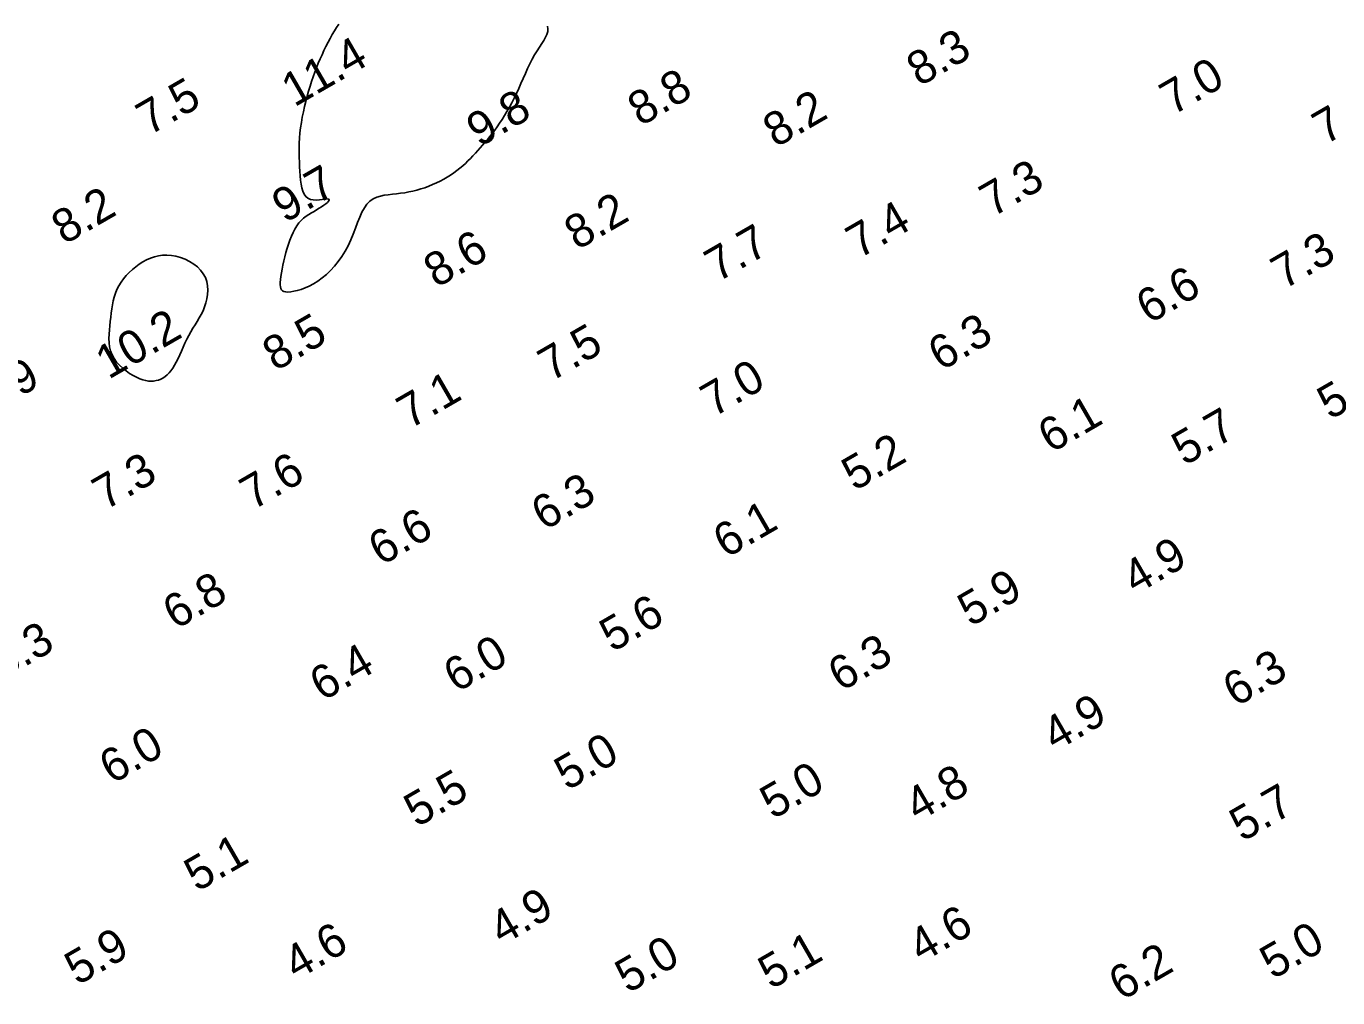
# Model space of a CAD drawing. Extents: x 3024098 to 3056816, y 418252 to 509144.
# Drawn here: x 3036706.3 to 3036901.9, y 419261.4 to 419406.4 of the extents above; entities that cross this region are included whole.
import ezdxf

# ---------------------------------------------------------------- set-up
doc = ezdxf.new("R2010")
doc.units = 0
doc.layers.add('V-CHAN-CONT-EL10', color=7, linetype='Continuous')
doc.layers.add('V-TOPO-SOUN-0911', color=7, linetype='Continuous')

msp = doc.modelspace()

# ---------------------------------------------------------------- linework, layer by layer
at = {"layer": 'V-CHAN-CONT-EL10'}
msp.add_lwpolyline([(3036784.03, 419406.41), (3036784.1, 419406.01), (3036784.07, 419405.6), (3036783.94, 419405.18), (3036783.74, 419404.74), (3036783.48, 419404.28), (3036783.17, 419403.79), (3036782.83, 419403.27), (3036782.47, 419402.71), (3036782.11, 419402.11), (3036781.75, 419401.47), (3036781.41, 419400.78), (3036781.07, 419400.06), (3036780.74, 419399.32), (3036780.41, 419398.57), (3036780.07, 419397.82), (3036779.74, 419397.08), (3036779.4, 419396.35), (3036779.05, 419395.64), (3036778.7, 419394.95), (3036778.34, 419394.29), (3036777.98, 419393.66), (3036777.62, 419393.05), (3036777.25, 419392.47), (3036776.88, 419391.92), (3036776.52, 419391.38), (3036776.15, 419390.88), (3036775.79, 419390.4), (3036775.42, 419389.93), (3036775.06, 419389.49), (3036774.7, 419389.06), (3036774.34, 419388.65), (3036773.98, 419388.24), (3036773.62, 419387.84), (3036773.27, 419387.45), (3036772.91, 419387.06), (3036772.54, 419386.67), (3036772.17, 419386.29), (3036771.78, 419385.92), (3036771.38, 419385.56), (3036770.96, 419385.2), (3036770.53, 419384.85), (3036770.06, 419384.51), (3036769.58, 419384.18), (3036769.07, 419383.86), (3036768.55, 419383.56), (3036768.01, 419383.27), (3036767.46, 419383), (3036766.9, 419382.75), (3036766.32, 419382.51), (3036765.74, 419382.3), (3036765.15, 419382.11), (3036764.55, 419381.94), (3036763.95, 419381.79), (3036763.34, 419381.66), (3036762.73, 419381.55), (3036762.12, 419381.46), (3036761.5, 419381.38), (3036760.89, 419381.31), (3036760.28, 419381.24), (3036759.68, 419381.16), (3036759.1, 419381.04), (3036758.55, 419380.86), (3036758.03, 419380.62), (3036757.54, 419380.28), (3036757.1, 419379.85), (3036756.71, 419379.29), (3036756.35, 419378.63), (3036756.02, 419377.89), (3036755.7, 419377.09), (3036755.38, 419376.24), (3036755.05, 419375.38), (3036754.69, 419374.5), (3036754.29, 419373.64), (3036753.84, 419372.82), (3036753.35, 419372.03), (3036752.81, 419371.29), (3036752.25, 419370.6), (3036751.65, 419369.95), (3036751.04, 419369.36), (3036750.41, 419368.83), (3036749.77, 419368.36), (3036749.12, 419367.96), (3036748.49, 419367.62), (3036747.87, 419367.35), (3036747.27, 419367.12), (3036746.71, 419366.95), (3036746.19, 419366.84), (3036745.72, 419366.76), (3036745.32, 419366.73), (3036744.98, 419366.74), (3036744.71, 419366.8), (3036744.51, 419366.89), (3036744.35, 419367.04), (3036744.25, 419367.24), (3036744.18, 419367.49), (3036744.16, 419367.8), (3036744.17, 419368.16), (3036744.2, 419368.59), (3036744.26, 419369.07), (3036744.34, 419369.6), (3036744.44, 419370.16), (3036744.56, 419370.76), (3036744.7, 419371.37), (3036744.86, 419372), (3036745.02, 419372.63), (3036745.2, 419373.26), (3036745.39, 419373.88), (3036745.6, 419374.48), (3036745.83, 419375.06), (3036746.07, 419375.61), (3036746.34, 419376.13), (3036746.62, 419376.61), (3036746.94, 419377.04), (3036747.28, 419377.41), (3036747.64, 419377.74), (3036748.02, 419378.04), (3036748.41, 419378.3), (3036748.81, 419378.54), (3036749.2, 419378.77), (3036749.59, 419378.99), (3036749.97, 419379.22), (3036750.33, 419379.45), (3036750.67, 419379.68), (3036750.96, 419379.91), (3036751.2, 419380.11), (3036751.37, 419380.3), (3036751.46, 419380.45), (3036751.46, 419380.56), (3036751.35, 419380.61), (3036751.13, 419380.62), (3036750.82, 419380.59), (3036750.43, 419380.54), (3036750, 419380.49), (3036749.54, 419380.46), (3036749.09, 419380.48), (3036748.66, 419380.56), (3036748.28, 419380.72), (3036747.97, 419380.98), (3036747.72, 419381.34), (3036747.53, 419381.77), (3036747.38, 419382.28), (3036747.27, 419382.84), (3036747.2, 419383.44), (3036747.14, 419384.08), (3036747.09, 419384.74), (3036747.05, 419385.42), (3036747.02, 419386.1), (3036746.99, 419386.79), (3036746.98, 419387.5), (3036746.98, 419388.22), (3036747, 419388.95), (3036747.04, 419389.7), (3036747.11, 419390.46), (3036747.2, 419391.23), (3036747.31, 419392.02), (3036747.45, 419392.81), (3036747.61, 419393.6), (3036747.78, 419394.39), (3036747.97, 419395.17), (3036748.17, 419395.94), (3036748.39, 419396.7), (3036748.61, 419397.43), (3036748.84, 419398.15), (3036749.08, 419398.85), (3036749.33, 419399.53), (3036749.58, 419400.2), (3036749.84, 419400.86), (3036750.12, 419401.51), (3036750.4, 419402.14), (3036750.69, 419402.77), (3036750.98, 419403.38), (3036751.29, 419403.99), (3036751.6, 419404.58), (3036751.92, 419405.14), (3036752.25, 419405.69), (3036752.58, 419406.22), (3036752.92, 419406.72)], dxfattribs=at)
msp.add_lwpolyline([(3036718.86, 419357.94), (3036718.71, 419358.54), (3036718.64, 419359.15), (3036718.61, 419359.78), (3036718.63, 419360.42), (3036718.67, 419361.07), (3036718.73, 419361.71), (3036718.8, 419362.35), (3036718.87, 419362.98), (3036718.94, 419363.6), (3036719.02, 419364.21), (3036719.12, 419364.81), (3036719.23, 419365.4), (3036719.38, 419365.98), (3036719.57, 419366.55), (3036719.8, 419367.1), (3036720.09, 419367.65), (3036720.42, 419368.18), (3036720.79, 419368.69), (3036721.2, 419369.18), (3036721.65, 419369.65), (3036722.12, 419370.09), (3036722.62, 419370.5), (3036723.14, 419370.88), (3036723.68, 419371.22), (3036724.23, 419371.52), (3036724.8, 419371.77), (3036725.39, 419371.98), (3036725.99, 419372.12), (3036726.62, 419372.21), (3036727.27, 419372.23), (3036727.93, 419372.19), (3036728.61, 419372.06), (3036729.3, 419371.87), (3036729.98, 419371.61), (3036730.63, 419371.29), (3036731.25, 419370.91), (3036731.8, 419370.48), (3036732.29, 419369.99), (3036732.69, 419369.46), (3036732.99, 419368.89), (3036733.19, 419368.29), (3036733.31, 419367.66), (3036733.35, 419367.03), (3036733.32, 419366.38), (3036733.23, 419365.74), (3036733.08, 419365.12), (3036732.89, 419364.52), (3036732.65, 419363.95), (3036732.38, 419363.4), (3036732.09, 419362.87), (3036731.78, 419362.35), (3036731.46, 419361.84), (3036731.14, 419361.32), (3036730.82, 419360.8), (3036730.51, 419360.25), (3036730.22, 419359.68), (3036729.94, 419359.1), (3036729.68, 419358.51), (3036729.42, 419357.92), (3036729.17, 419357.35), (3036728.92, 419356.8), (3036728.66, 419356.28), (3036728.4, 419355.8), (3036728.14, 419355.37), (3036727.86, 419354.98), (3036727.58, 419354.65), (3036727.28, 419354.36), (3036726.98, 419354.11), (3036726.66, 419353.9), (3036726.33, 419353.73), (3036725.99, 419353.6), (3036725.65, 419353.51), (3036725.28, 419353.45), (3036724.9, 419353.43), (3036724.51, 419353.45), (3036724.09, 419353.52), (3036723.66, 419353.64), (3036723.2, 419353.8), (3036722.71, 419354.01), (3036722.21, 419354.28), (3036721.68, 419354.59), (3036721.16, 419354.96), (3036720.66, 419355.36), (3036720.18, 419355.81), (3036719.75, 419356.29), (3036719.38, 419356.81), (3036719.08, 419357.36)], close=True, dxfattribs=at)

# ---------------------------------------------------------------- texts
at = {"layer": 'V-TOPO-SOUN-0911'}
for s, p in [('8.3', (3036839.51, 419397.32)), ('11.4 ', (3036746.27, 419394.26)), ('8.8', (3036797.91, 419391.38)), ('7.0', (3036877.29, 419393.02)), ('7.5', (3036724.61, 419390.01)), ('9.8', (3036773.87, 419388.27)), ('8.2', (3036818.09, 419388.2)), ('7.9', (3036900.05, 419388.63)), ('7.3', (3036850.41, 419377.83)), ('9.7', (3036744.86, 419376.95)), ('8.2', (3036711.96, 419373.73)), ('8.2', (3036788.46, 419372.91)), ('7.4', (3036830.49, 419371.63)), ('7.7', (3036809.4, 419368.12)), ('8.6', (3036767.47, 419367.28)), ('7.3', (3036893.88, 419367.04)), ('6.6', (3036873.76, 419361.89)), ('10.2 ', (3036718.55, 419353.62)), ('8.5', (3036743.44, 419354.84)), ('6.3', (3036842.73, 419354.87)), ('7.5', (3036784.55, 419353.29)), ('7.9', (3036700.57, 419348.27)), ('7.0', (3036808.79, 419347.98)), ('5.9', (3036900.77, 419347.58)), ('7.1', (3036763.48, 419346.22)), ('6.1', (3036859.12, 419342.61)), ('5.7', (3036879.05, 419340.73)), ('5.2', (3036829.84, 419336.96)), ('7.3', (3036718.06, 419334.1)), ('7.6', (3036740.07, 419334.11)), ('6.3', (3036783.54, 419331.05)), ('6.1', (3036810.66, 419326.93)), ('6.6', (3036759.23, 419325.81)), ('4.9', (3036871.73, 419321.5)), ('6.8', (3036728.56, 419316.29)), ('5.9', (3036847.13, 419316.71)), ('5.6', (3036793.71, 419312.91)), ('5.3', (3036702.74, 419308.87)), ('6.4', (3036750.47, 419305.59)), ('6.0', (3036770.44, 419306.87)), ('6.3', (3036827.8, 419307.03)), ('6.3', (3036886.69, 419304.74)), ('4.9', (3036859.76, 419298.11)), ('6.0', (3036719.09, 419293.22)), ('5.0', (3036786.97, 419292.27)), ('5.0', (3036817.65, 419287.97)), ('4.8', (3036839.25, 419287.58)), ('5.5', (3036764.54, 419286.79)), ('5.7', (3036887.68, 419284.63)), ('5.1', (3036731.75, 419277.16)), ('4.9', (3036777.24, 419269.17)), ('4.6', (3036839.78, 419266.55)), ('4.6', (3036746.57, 419263.99)), ('5.0', (3036892.22, 419264.09)), ('5.9', (3036713.92, 419263.2)), ('5.0', (3036796.03, 419262.02)), ('5.1', (3036817.38, 419262.59)), ('6.2', (3036869.67, 419260.91))]:
    msp.add_text(s, height=5, rotation=30, dxfattribs=at).set_placement(p)

doc.saveas('drawing.dxf')
